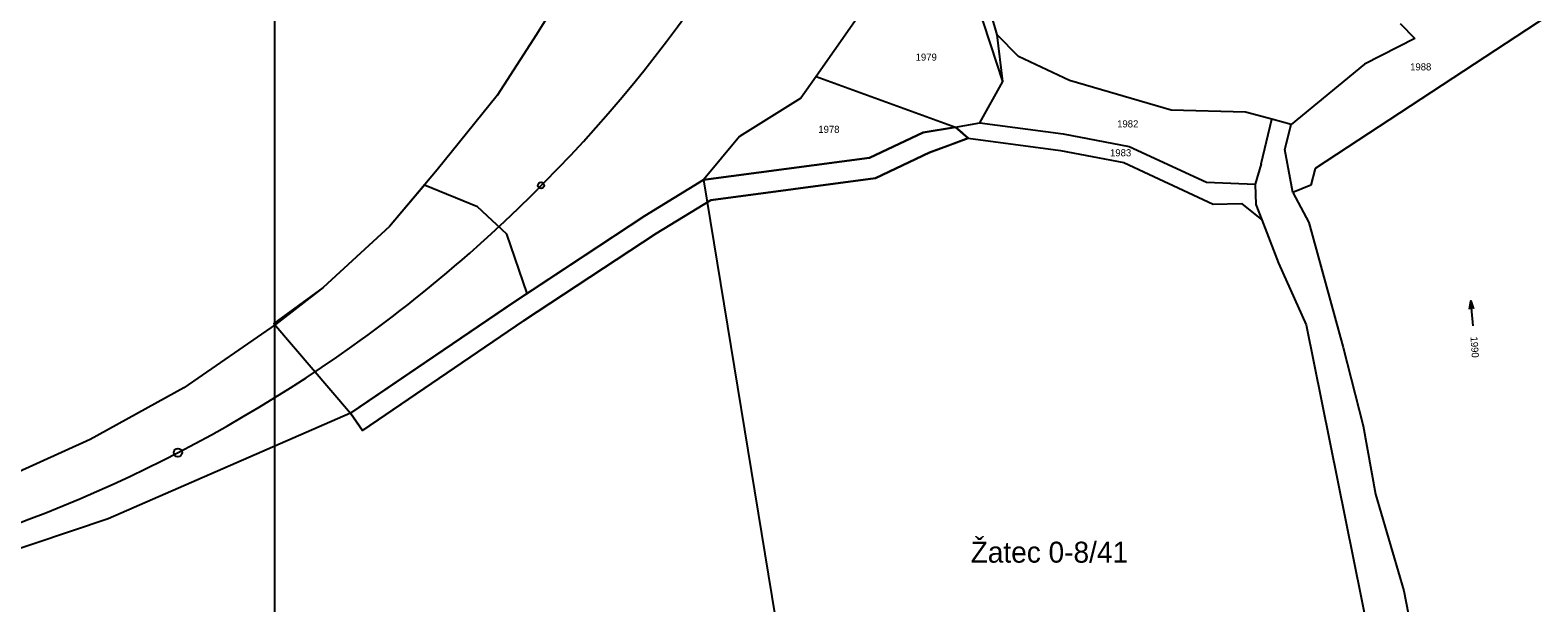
# Model space of a CAD drawing. Extents: x -802857 to -799647, y -1020285 to -1015884.
# Drawn here: x -801308.3 to -800948.7, y -1017248.9 to -1017112.3 of the extents above; entities that cross this region are included whole.
import ezdxf

# ---------------------------------------------------------------- set-up
doc = ezdxf.new("R2010")
doc.units = 0
for name, color, linetype in [('05a - kolej - svršek', 7, 'Continuous'), ('Default', 7, 'Continuous'), ('dočasné zábory', 7, 'Continuous'), ('KLADY_ZMVM', 7, 'Continuous'), ('KN_HRANICE', 7, 'Continuous'), ('KN_KULTURY', 7, 'Continuous'), ('KN_PARCELY', 7, 'Continuous'), ('obvod_stavby', 7, 'Continuous'), ('Svršek_hkm_100', 7, 'Continuous'), ('Železniční svršek', 7, 'Continuous')]:
    doc.layers.add(name, color=color, linetype=linetype)

# ---------------------------------------------------------------- blocks, each defined once
blk = doc.blocks.new('802')
at = {"layer": 'Default'}
blk.add_line((-3, 0), (3, 0), dxfattribs=at)
blk.add_lwpolyline([(1, 0.5), (3, 0), (1, -0.5)], dxfattribs=at)
blk = doc.blocks.new('C513')
at = {"layer": 'Default'}
blk.add_circle((0, 0), 0.75, dxfattribs=at)

msp = doc.modelspace()

# ---------------------------------------------------------------- linework, layer by layer
at = {"layer": 'dočasné zábory'}
msp.add_lwpolyline([(-801087.64, -1017135.44), (-801086.11, -1017136.78), (-801084.58, -1017138.12), (-801089.18, -1017139.83), (-801093.79, -1017141.54), (-801106.71, -1017147.66), (-801145.96, -1017152.86), (-801158.99, -1017160.82), (-801187.37, -1017179.55), (-801190.6, -1017181.7), (-801229.06, -1017207.85), (-801231.87, -1017203.72), (-801193.39, -1017177.55), (-801190.13, -1017175.38), (-801161.67, -1017156.6), (-801147.67, -1017148.04), (-801108.14, -1017142.81), (-801095.3, -1017136.72), (-801087.64, -1017135.44)], dxfattribs=at)
at = {"layer": 'KLADY_ZMVM'}
msp.add_lwpolyline([(-801250, -1017000), (-801250, -1017500), (-801250, -1018000)], dxfattribs=at)
at = {"layer": 'KN_HRANICE'}
for p, q in [((-801179.48, -1017100.28), (-801187.5, -1017113.35)), ((-801107.38, -1017104.16), (-801120.85, -1017123.38)), ((-800941.26, -1017105.59), (-801001.86, -1017145.37)), ((-801077.69, -1017113.44), (-801079.03, -1017108.8)), ((-801079.17, -1017115.86), (-801081.08, -1017110)), ((-800981.55, -1017110.76), (-800978.03, -1017114.36)), ((-801187.5, -1017113.35), (-801196.91, -1017127.94)), ((-801076.29, -1017124.55), (-801079.17, -1017115.86)), ((-801076.29, -1017124.55), (-801077.69, -1017113.44)), ((-801072.61, -1017118.61), (-801077.69, -1017113.44)), ((-800978.03, -1017114.36), (-800990.08, -1017120.48)), ((-801060.39, -1017124.37), (-801072.61, -1017118.61)), ((-801120.85, -1017123.38), (-801124.46, -1017128.53)), ((-801120.85, -1017123.38), (-801087.64, -1017135.44)), ((-800990.08, -1017120.48), (-801007.59, -1017134.85)), ((-801081.77, -1017134.46), (-801076.29, -1017124.55)), ((-801036.16, -1017131.43), (-801060.39, -1017124.37)), ((-801196.91, -1017127.94), (-801211.22, -1017145.68)), ((-801124.46, -1017128.53), (-801139.16, -1017137.71)), ((-801087.64, -1017135.44), (-801081.77, -1017134.46)), ((-801081.77, -1017134.46), (-801061.94, -1017137.05)), ((-801018.45, -1017131.86), (-801036.16, -1017131.43)), ((-801012.13, -1017133.6), (-801018.45, -1017131.86)), ((-801014.73, -1017144.22), (-801012.13, -1017133.6)), ((-801007.59, -1017134.85), (-801012.13, -1017133.6)), ((-801139.16, -1017137.71), (-801147.67, -1017148.04)), ((-801095.3, -1017136.72), (-801108.14, -1017142.81)), ((-801095.3, -1017136.72), (-801087.64, -1017135.44)), ((-801087.64, -1017135.44), (-801084.58, -1017138.12)), ((-801084.58, -1017138.12), (-801062.58, -1017141)), ((-801061.94, -1017137.05), (-801046.19, -1017140.07)), ((-801009.05, -1017140.81), (-801007.59, -1017134.85)), ((-801062.58, -1017141), (-801047.43, -1017143.9)), ((-801046.19, -1017140.07), (-801027.73, -1017148.59)), ((-801007.17, -1017151.05), (-801009.05, -1017140.81)), ((-801108.14, -1017142.81), (-801147.67, -1017148.04)), ((-801047.43, -1017143.9), (-801026.14, -1017153.86)), ((-801014.73, -1017144.22), (-801016.11, -1017149.08)), ((-801001.86, -1017145.37), (-801002.87, -1017149.33)), ((-801211.22, -1017145.68), (-801222.62, -1017159.13)), ((-801147.67, -1017148.04), (-801161.67, -1017156.6)), ((-801147.67, -1017148.04), (-801120.7, -1017312.51)), ((-801027.73, -1017148.59), (-801016.11, -1017149.08)), ((-801016.11, -1017149.08), (-801015.97, -1017153.92)), ((-801002.87, -1017149.33), (-801007.17, -1017151.05)), ((-801007.17, -1017151.05), (-801003.34, -1017158.2)), ((-801026.14, -1017153.86), (-801019.43, -1017153.68)), ((-801019.43, -1017153.68), (-801014.57, -1017157.55)), ((-801015.97, -1017153.92), (-801014.57, -1017157.55)), ((-801222.62, -1017159.13), (-801238.45, -1017173.69)), ((-801161.67, -1017156.6), (-801192.33, -1017176.83)), ((-801014.57, -1017157.55), (-801010.59, -1017167.92)), ((-801003.34, -1017158.2), (-800995.15, -1017188.06)), ((-801010.59, -1017167.92), (-801003.97, -1017182.58)), ((-801238.45, -1017173.69), (-801249.76, -1017182.55)), ((-801192.33, -1017176.83), (-801231.87, -1017203.72)), ((-801249.76, -1017182.55), (-801271.65, -1017197.67)), ((-801003.97, -1017182.58), (-800982.5, -1017289.15)), ((-800995.15, -1017188.06), (-800990.37, -1017206.68)), ((-801271.65, -1017197.67), (-801294.01, -1017209.98)), ((-801231.87, -1017203.72), (-801289.7, -1017228.88)), ((-801294.01, -1017209.98), (-801312.74, -1017218.5)), ((-800990.37, -1017206.68), (-800987.47, -1017223.03)), ((-800987.47, -1017223.03), (-800980.69, -1017246.06)), ((-801289.7, -1017228.88), (-801318.92, -1017238.69)), ((-800980.69, -1017246.06), (-800976.35, -1017268.19))]:
    msp.add_line(p, q, dxfattribs=at)
at = {"layer": 'obvod_stavby'}
msp.add_lwpolyline([(-801087.64, -1017135.44), (-801095.3, -1017136.72), (-801108.14, -1017142.81), (-801147.67, -1017148.04), (-801161.67, -1017156.6), (-801189.73, -1017175.11), (-801194.62, -1017160.96), (-801201.6, -1017154.44), (-801214.28, -1017149.29), (-801222.62, -1017159.13), (-801238.45, -1017173.69), (-801250.19, -1017182.28), (-801231.87, -1017203.72), (-801229.06, -1017207.85), (-801190.6, -1017181.7), (-801158.99, -1017160.82), (-801145.96, -1017152.86), (-801106.71, -1017147.66), (-801093.79, -1017141.54), (-801084.58, -1017138.12), (-801087.64, -1017135.44)], dxfattribs=at)
at = {"layer": 'Svršek_hkm_100'}
msp.add_circle((-801273.05, -1017213.08), 1, dxfattribs=at)
at = {"layer": 'Železniční svršek'}
for start, end in [(311.7457, 358.6036), (305.4132, 311.7457), (259.1164, 305.4132)]:
    msp.add_arc((-801431.93, -1016905.94), 345.8, start, end, dxfattribs=at)

# ---------------------------------------------------------------- block references
at = {"layer": '05a - kolej - svršek', "rotation": -134.7448899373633}
msp.add_blockref('C513', (-801186.44, -1017149.36), dxfattribs=at)
at = {"layer": 'KN_KULTURY', "rotation": 95.512064}
msp.add_blockref('802', (-800964.44, -1017179.86), dxfattribs=at)

# ---------------------------------------------------------------- texts
at = {"layer": 'KLADY_ZMVM'}
msp.add_text('Žatec 0-8/41', height=5, dxfattribs=at).set_placement((-801083.99, -1017239.34))
at = {"layer": 'KN_PARCELY'}
for s, p in [('1979', (-801097.12, -1017119.62)), ('1988', (-800979.19, -1017121.94)), ('1982', (-801049.06, -1017135.54)), ('1978', (-801120.33, -1017136.85)), ('1983', (-801050.76, -1017142.43))]:
    msp.add_text(s, height=1.7, dxfattribs=at).set_placement(p)
msp.add_text('1990', height=1.7, rotation=273.759, dxfattribs=at).set_placement((-800964.8, -1017185.47))

doc.saveas('drawing.dxf')
